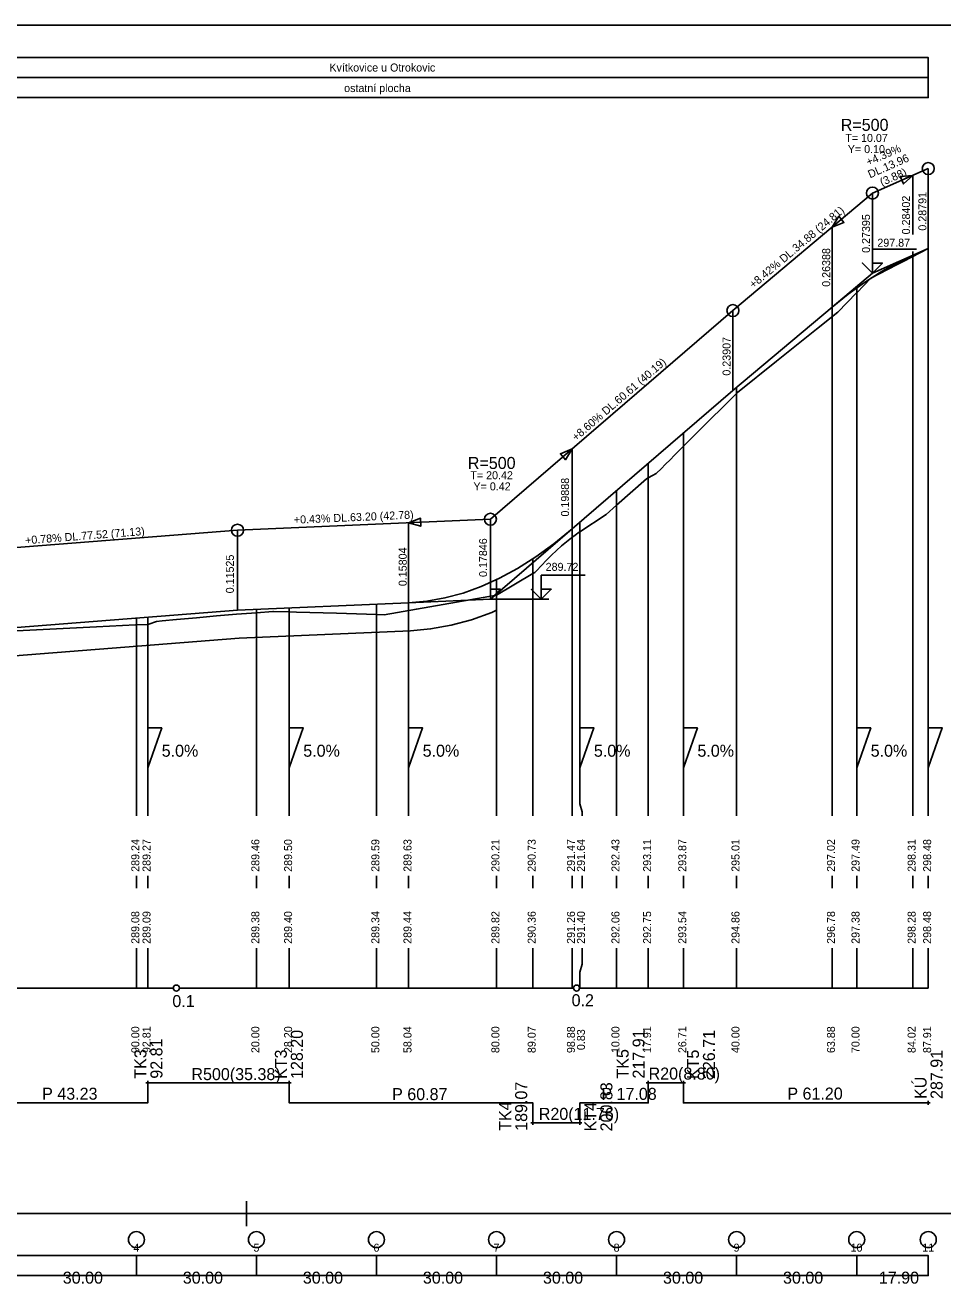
# Model space of a CAD drawing. Extents: x -261.5 to -198.5, y 150.1 to 181.6.
# Drawn here: x -246.01 to -223.08, y 150.11 to 181.57 of the extents above; entities that cross this region are included whole.
import ezdxf

# ---------------------------------------------------------------- set-up
doc = ezdxf.new("R2010")
doc.units = 0
for name, color, linetype in [('_drenaz', 7, 'Continuous'), ('KOTA', 7, 'Continuous'), ('NOVY_STAV', 7, 'Continuous'), ('NS_OBLOUK', 7, 'Continuous'), ('REZY_PO', 7, 'Continuous'), ('SESTAVY_REZU_PO', 7, 'Continuous'), ('SKLONOVE_POMERY', 7, 'Continuous'), ('SMEROVE_POMERY', 7, 'Continuous'), ('SMEROVE_POMERY_KOD', 7, 'Continuous'), ('SVK_STAT', 7, 'Continuous'), ('TABULKY', 7, 'Continuous'), ('u_pricne_rezy', 7, 'Continuous'), ('x_formát_rám', 7, 'Continuous')]:
    doc.layers.add(name, color=color, linetype=linetype)

msp = doc.modelspace()

# ---------------------------------------------------------------- linework, layer by layer
at = {"layer": '_drenaz'}
msp.add_lwpolyline([(-251.082, 165.262), (-249.001, 165.558), (-248.689, 165.6), (-248.381, 165.636), (-248.072, 165.668), (-247.761, 165.694), (-240.663, 166.249), (-236.381, 166.435), (-235.88, 166.48), (-235.366, 166.572), (-234.855, 166.71), (-234.348, 166.893), (-234.231, 166.946)], dxfattribs=at)
at = {"layer": 'KOTA'}
msp.add_line((-234.385, 167.222), (-232.92, 167.222), dxfattribs=at)
for points in [[(-224.836, 175.375), (-225.086, 175.625), (-224.836, 175.375), (-224.836, 175.975), (-223.736, 175.975)], [(-224.836, 175.625), (-224.836, 175.375), (-224.586, 175.625), (-224.836, 175.625)], [(-224.836, 175.375), (-224.586, 175.625), (-224.836, 175.625)], [(-224.836, 175.375), (-224.836, 175.375)], [(-233.112, 167.222), (-233.362, 167.472), (-233.112, 167.222), (-233.112, 167.822), (-232.012, 167.822)], [(-234.385, 167.222), (-234.135, 167.472), (-234.385, 167.472)], [(-233.112, 167.472), (-233.112, 167.222), (-232.862, 167.472), (-233.112, 167.472)], [(-234.385, 167.222), (-234.385, 167.222)]]:
    msp.add_lwpolyline(points, dxfattribs=at)
at = {"layer": 'NOVY_STAV'}
for points in [[(-224.836, 177.375), (-223.44, 177.988)], [(-223.44, 175.988), (-223.44, 177.988)], [(-228.324, 174.437), (-224.836, 177.375)], [(-224.836, 175.375), (-224.836, 177.375)], [(-247.818, 166.392), (-240.705, 166.948), (-236.427, 167.134), (-235.973, 167.174), (-235.519, 167.256), (-235.065, 167.378), (-234.612, 167.542), (-234.158, 167.747), (-233.704, 167.993), (-233.25, 168.281), (-232.796, 168.609), (-232.343, 168.979), (-228.324, 172.437), (-225.843, 174.526), (-225.44, 174.849), (-225.037, 175.14), (-224.634, 175.398), (-224.231, 175.624), (-223.828, 175.817), (-223.44, 175.988)], [(-225.843, 174.526), (-224.836, 175.375), (-223.44, 175.988)], [(-234.385, 169.222), (-228.324, 174.437)], [(-228.324, 172.437), (-228.324, 174.437)], [(-248.457, 168.342), (-240.705, 168.948)], [(-240.705, 168.948), (-234.385, 169.222)], [(-240.705, 166.948), (-240.705, 168.948)], [(-236.427, 167.134), (-234.385, 167.222), (-232.343, 168.979), (-232.343, 168.979)], [(-234.385, 167.222), (-234.385, 169.222)]]:
    msp.add_lwpolyline(points, dxfattribs=at)
for centre in [(-223.44, 177.988), (-224.836, 177.375), (-228.324, 174.437), (-234.385, 169.222), (-240.705, 168.948)]:
    msp.add_circle(centre, 0.15, dxfattribs=at)
at = {"layer": 'NS_OBLOUK'}
for points in [[(-224.063, 177.605), (-223.828, 177.817), (-224.143, 177.788), (-224.063, 177.605)], [(-223.828, 176.336), (-223.828, 177.817)], [(-225.843, 176.526), (-225.549, 176.643), (-225.678, 176.796), (-225.843, 176.526)], [(-225.843, 174.526), (-225.843, 176.526)], [(-223.828, 175.817), (-223.828, 175.914)], [(-232.505, 170.708), (-232.343, 170.979), (-232.635, 170.859), (-232.505, 170.708)], [(-232.343, 168.979), (-232.343, 170.979)], [(-236.427, 169.134), (-236.123, 169.047), (-236.131, 169.247), (-236.427, 169.134)], [(-236.427, 167.134), (-236.427, 169.134)]]:
    msp.add_lwpolyline(points, dxfattribs=at)
for points in [[(-223.828, 177.817), (-224.143, 177.788), (-224.063, 177.605)], [(-225.843, 176.526), (-225.678, 176.796), (-225.549, 176.643)], [(-232.343, 170.979), (-232.635, 170.859), (-232.505, 170.708)], [(-236.427, 169.134), (-236.131, 169.247), (-236.123, 169.047)]]:
    msp.add_lwpolyline(points, close=True, dxfattribs=at)
at = {"layer": 'REZY_PO'}
msp.add_lwpolyline([(-246.231, 166.433), (-245.231, 166.485), (-244.231, 166.536), (-243.251, 166.586), (-243.231, 166.587), (-243.231, 166.587), (-242.949, 166.595), (-242.921, 166.596), (-242.733, 166.666), (-242.59, 166.68), (-242.231, 166.715), (-241.731, 166.761), (-241.231, 166.805), (-240.731, 166.847), (-240.231, 166.887), (-240.231, 166.887), (-240.231, 166.887), (-239.821, 166.918), (-239.806, 166.919), (-239.411, 166.907), (-239.231, 166.902), (-238.231, 166.871), (-237.231, 166.841), (-237.231, 166.841), (-237.039, 166.835), (-236.231, 166.976), (-235.231, 167.15), (-234.232, 167.324), (-234.231, 167.325), (-234.231, 167.325), (-233.323, 167.865), (-233.277, 167.893), (-233.259, 167.904), (-233.231, 167.936), (-233.106, 168.07), (-232.981, 168.199), (-232.856, 168.323), (-232.731, 168.442), (-232.606, 168.554), (-232.481, 168.66), (-232.356, 168.759), (-232.231, 168.85), (-232.189, 168.879), (-232.147, 168.907), (-231.492, 169.34), (-231.231, 169.571), (-231.23, 169.571), (-230.48, 170.233), (-230.439, 170.256), (-230.439, 170.256), (-230.439, 170.256), (-230.335, 170.314), (-230.241, 170.365), (-230.231, 170.375), (-230.119, 170.486), (-230.007, 170.598), (-229.895, 170.71), (-229.783, 170.823), (-229.672, 170.935), (-229.56, 171.047), (-229.56, 171.047), (-229.56, 171.047), (-229.231, 171.374), (-228.231, 172.369), (-228.23, 172.369), (-228.209, 172.391), (-227.231, 173.172), (-226.231, 173.972), (-225.697, 174.398), (-225.231, 174.881), (-225.23, 174.882), (-224.878, 175.246), (-224.231, 175.581), (-224.065, 175.666), (-223.44, 175.988)], dxfattribs=at)
at = {"layer": 'SESTAVY_REZU_PO'}
for points in [[(-255.634, 157.506), (-242.306, 157.506)], [(-242.156, 157.506), (-232.306, 157.506)], [(-232.156, 157.506), (-223.44, 157.506)]]:
    msp.add_lwpolyline(points, dxfattribs=at)
for centre in [(-242.231, 157.506), (-232.231, 157.506)]:
    msp.add_circle(centre, 0.075, dxfattribs=at)
at = {"layer": 'SMEROVE_POMERY'}
for points in [[(-242.949, 164.006), (-242.949, 163.006), (-242.949, 163.006), (-242.774, 163.506), (-242.599, 164.006), (-242.949, 164.006)], [(-239.411, 164.006), (-239.411, 163.006), (-239.411, 163.006), (-239.236, 163.506), (-239.061, 164.006), (-239.411, 164.006)], [(-236.427, 164.006), (-236.427, 163.006), (-236.427, 163.006), (-236.252, 163.506), (-236.077, 164.006), (-236.427, 164.006)], [(-232.147, 164.006), (-232.147, 163.006), (-232.147, 163.006), (-231.972, 163.506), (-231.797, 164.006), (-232.147, 164.006)], [(-229.56, 164.006), (-229.56, 163.006), (-229.56, 163.006), (-229.385, 163.506), (-229.21, 164.006), (-229.56, 164.006)], [(-225.23, 164.006), (-225.23, 163.006), (-225.23, 163.006), (-225.055, 163.506), (-224.88, 164.006), (-225.23, 164.006)], [(-223.44, 164.006), (-223.44, 163.006), (-223.44, 163.006), (-223.265, 163.506), (-223.09, 164.006), (-223.44, 164.006)], [(-252.231, 154.633), (-251.699, 154.633), (-251.699, 154.133), (-250.467, 154.133), (-250.467, 154.633), (-249.199, 154.633), (-249.199, 154.133), (-247.272, 154.133), (-247.272, 154.633), (-242.949, 154.633), (-242.949, 155.133), (-239.411, 155.133), (-239.411, 154.633), (-233.323, 154.633), (-233.323, 154.133), (-232.147, 154.133), (-232.147, 154.633), (-230.439, 154.633), (-230.439, 155.133), (-229.56, 155.133), (-229.56, 154.633), (-223.44, 154.633)]]:
    msp.add_lwpolyline(points, dxfattribs=at)
at = {"layer": 'SMEROVE_POMERY_KOD'}
for points in [[(-242.999, 155.133), (-242.899, 155.133)], [(-242.949, 155.083), (-242.949, 155.183)], [(-239.461, 155.133), (-239.361, 155.133)], [(-239.411, 155.083), (-239.411, 155.183)], [(-230.489, 155.133), (-230.389, 155.133)], [(-230.439, 155.083), (-230.439, 155.183)], [(-229.61, 155.133), (-229.51, 155.133)], [(-229.56, 155.083), (-229.56, 155.183)], [(-223.49, 154.633), (-223.39, 154.633)], [(-223.44, 154.583), (-223.44, 154.683)], [(-233.323, 154.083), (-233.323, 154.183)], [(-232.147, 154.083), (-232.147, 154.183)], [(-233.373, 154.133), (-233.273, 154.133)], [(-232.197, 154.133), (-232.097, 154.133)]]:
    msp.add_lwpolyline(points, dxfattribs=at)
at = {"layer": 'SVK_STAT'}
for points in [[(-223.44, 161.806), (-223.44, 175.988)], [(-223.828, 161.806), (-223.828, 175.817)], [(-225.23, 161.806), (-225.23, 175)], [(-225.843, 161.806), (-225.843, 174.526)], [(-228.23, 161.806), (-228.23, 172.515)], [(-229.56, 161.806), (-229.56, 171.373)], [(-230.439, 161.806), (-230.439, 170.616)], [(-231.23, 161.806), (-231.23, 169.936)], [(-232.343, 161.806), (-232.343, 168.979)], [(-232.093, 161.806), (-232.093, 161.906), (-232.147, 162.106), (-232.147, 169.147)], [(-233.323, 161.806), (-233.323, 168.234)], [(-234.231, 161.806), (-234.231, 167.714)], [(-237.231, 161.806), (-237.231, 167.099)], [(-236.427, 161.806), (-236.427, 167.134)], [(-243.231, 161.806), (-243.231, 166.751)], [(-242.949, 161.806), (-242.949, 166.773)], [(-240.231, 161.806), (-240.231, 166.969)], [(-239.411, 161.806), (-239.411, 167.004)], [(-243.231, 160.006), (-243.231, 160.306)], [(-242.949, 160.006), (-242.949, 160.306)], [(-240.231, 160.006), (-240.231, 160.306)], [(-239.411, 160.006), (-239.411, 160.306)], [(-237.231, 160.006), (-237.231, 160.306)], [(-236.427, 160.006), (-236.427, 160.306)], [(-234.231, 160.006), (-234.231, 160.306)], [(-233.323, 160.006), (-233.323, 160.306)], [(-232.343, 160.006), (-232.343, 160.306)], [(-232.093, 160.006), (-232.093, 160.306)], [(-231.23, 160.006), (-231.23, 160.306)], [(-230.439, 160.006), (-230.439, 160.306)], [(-229.56, 160.006), (-229.56, 160.306)], [(-228.23, 160.006), (-228.23, 160.306)], [(-225.843, 160.006), (-225.843, 160.306)], [(-225.23, 160.006), (-225.23, 160.306)], [(-223.828, 160.006), (-223.828, 160.306)], [(-223.44, 160.006), (-223.44, 160.306)], [(-243.231, 157.506), (-243.231, 158.506)], [(-242.949, 157.506), (-242.949, 158.506)], [(-240.231, 157.506), (-240.231, 158.506)], [(-239.411, 157.506), (-239.411, 158.506)], [(-237.231, 157.506), (-237.231, 158.506)], [(-236.427, 157.506), (-236.427, 158.506)], [(-234.231, 157.506), (-234.231, 158.506)], [(-233.323, 157.506), (-233.323, 158.506)], [(-232.343, 157.506), (-232.343, 158.506)], [(-232.147, 157.506), (-232.147, 157.906), (-232.093, 158.106), (-232.093, 158.506)], [(-231.23, 157.506), (-231.23, 158.506)], [(-230.439, 157.506), (-230.439, 158.506)], [(-229.56, 157.506), (-229.56, 158.506)], [(-228.23, 157.506), (-228.23, 158.506)], [(-225.843, 157.506), (-225.843, 158.506)], [(-225.23, 157.506), (-225.23, 158.506)], [(-223.828, 157.506), (-223.828, 158.506)], [(-223.44, 157.506), (-223.44, 158.506)]]:
    msp.add_lwpolyline(points, dxfattribs=at)
at = {"layer": 'TABULKY'}
for points in [[(-252.231, 179.76), (-223.44, 179.76), (-223.44, 180.76), (-252.231, 180.76), (-252.231, 179.76)], [(-252.231, 180.26), (-223.44, 180.26)]]:
    msp.add_lwpolyline(points, dxfattribs=at)
at = {"layer": 'u_pricne_rezy'}
for points in [[(-252.231, 150.317), (-223.44, 150.317), (-223.44, 150.817), (-252.231, 150.817), (-252.231, 150.317)], [(-243.231, 150.317), (-243.231, 150.817)], [(-240.231, 150.317), (-240.231, 150.817)], [(-237.231, 150.317), (-237.231, 150.817)], [(-234.231, 150.317), (-234.231, 150.817)], [(-231.23, 150.317), (-231.23, 150.817)], [(-228.23, 150.317), (-228.23, 150.817)], [(-225.23, 150.317), (-225.23, 150.817)]]:
    msp.add_lwpolyline(points, dxfattribs=at)
for centre in [(-243.231, 151.217), (-240.231, 151.217), (-237.231, 151.217), (-234.231, 151.217), (-231.23, 151.217), (-228.23, 151.217), (-225.23, 151.217), (-223.44, 151.217)]:
    msp.add_circle(centre, 0.2, dxfattribs=at)
at = {"layer": 'x_formát_rám'}
msp.add_line((-240.476, 152.183), (-240.476, 151.558), dxfattribs=at)
msp.add_lwpolyline([(-261.476, 151.871), (-198.476, 151.871), (-198.476, 181.571), (-261.476, 181.571)], close=True, dxfattribs=at)

# ---------------------------------------------------------------- texts
at = {"layer": 'KOTA'}
for s, p in [('297.87', (-224.713, 176.034)), ('289.72', (-233.003, 167.933))]:
    msp.add_text(s, height=0.2, dxfattribs=at).set_placement(p)
at = {"layer": 'NOVY_STAV'}
for s, rotation, p in [('+4.39%', 23.7149, (-224.938, 178.05)), ('DL.13.96', 23.7149, (-224.896, 177.741)), ('(3.88)', 23.7149, (-224.597, 177.544)), (' 0.28791', 90, (-223.488, 176.361)), ('+8.42% DL.34.88 (24.81)', 40.1057, (-227.81, 174.982)), (' 0.27395', 90, (-224.897, 175.805)), (' 0.23907', 90, (-228.382, 172.737)), ('+8.60% DL.60.61 (40.19)', 40.7045, (-232.243, 171.166)), ('+0.43% DL.63.20 (42.78)', 2.4868, (-239.292, 169.109)), ('+0.78% DL.77.52 (71.13)', 4.4694, (-246.005, 168.595)), (' 0.17846', 90, (-234.468, 167.705)), (' 0.11525', 90, (-240.795, 167.297))]:
    msp.add_text(s, height=0.2, rotation=rotation, dxfattribs=at).set_placement(p)
at = {"layer": 'NS_OBLOUK'}
for s, height, p in [('R=500', 0.3, (-225.628, 178.93)), ('T= 10.07', 0.2, (-225.515, 178.653)), ('Y= 0.10', 0.2, (-225.452, 178.374)), ('R=500', 0.3, (-234.948, 170.479)), ('T= 20.42', 0.2, (-234.885, 170.222)), ('Y= 0.42', 0.2, (-234.807, 169.944))]:
    msp.add_text(s, height=height, dxfattribs=at).set_placement(p)
for s, p in [(' 0.28402', (-223.897, 176.268)), (' 0.26388', (-225.892, 174.958)), (' 0.19888', (-232.419, 169.216)), (' 0.15804', (-236.476, 167.476))]:
    msp.add_text(s, height=0.2, rotation=90, dxfattribs=at).set_placement(p)
at = {"layer": 'SESTAVY_REZU_PO'}
for s, p in [('0.1', (-242.333, 157.03)), ('0.2', (-232.354, 157.051))]:
    msp.add_text(s, height=0.3, dxfattribs=at).set_placement(p)
at = {"layer": 'SKLONOVE_POMERY'}
for p in [(-242.599, 163.287), (-239.061, 163.287), (-236.077, 163.287), (-231.797, 163.287), (-229.21, 163.287), (-224.88, 163.287)]:
    msp.add_text('5.0%', height=0.3, dxfattribs=at).set_placement(p)
at = {"layer": 'SMEROVE_POMERY'}
for s, p in [('R500(35.38)', (-241.856, 155.204)), ('R20(8.80)', (-230.43, 155.218)), ('P 43.23', (-245.587, 154.715)), ('P 60.87', (-236.84, 154.704)), ('P 17.08', (-231.611, 154.711)), ('P 61.20', (-226.962, 154.718)), ('R20(11.76)', (-233.174, 154.211))]:
    msp.add_text(s, height=0.3, dxfattribs=at).set_placement(p)
at = {"layer": 'SMEROVE_POMERY_KOD'}
for s, p in [('128.20', (-239.071, 155.233)), ('217.91', (-230.529, 155.244)), ('226.71', (-228.772, 155.23)), ('92.81', (-242.581, 155.24)), ('TK3', (-242.981, 155.24)), ('KT3', (-239.471, 155.233)), ('TK5', (-230.929, 155.244)), ('KT5', (-229.172, 155.23)), ('287.91', (-223.084, 154.733)), ('189.07', (-233.465, 153.937)), ('200.83', (-231.335, 153.923)), ('KÚ', (-223.484, 154.733)), ('TK4', (-233.865, 153.937)), ('KT4', (-231.735, 153.923))]:
    msp.add_text(s, height=0.3, rotation=90, dxfattribs=at).set_placement(p)
at = {"layer": 'SVK_STAT'}
for s, p in [(' 289.24', (-243.159, 160.336)), (' 289.27', (-242.878, 160.336)), (' 289.46', (-240.159, 160.336)), (' 289.50', (-239.34, 160.336)), (' 289.59', (-237.159, 160.336)), (' 289.63', (-236.356, 160.336)), (' 290.21', (-234.159, 160.336)), (' 290.73', (-233.252, 160.336)), (' 291.47', (-232.271, 160.336)), (' 291.64', (-232.021, 160.336)), (' 292.43', (-231.159, 160.336)), (' 293.11', (-230.368, 160.336)), (' 293.87', (-229.489, 160.336)), (' 295.01', (-228.159, 160.336)), (' 297.02', (-225.772, 160.336)), (' 297.49', (-225.159, 160.336)), (' 298.31', (-223.757, 160.336)), (' 298.48', (-223.369, 160.336)), (' 289.08', (-243.159, 158.536)), (' 289.09', (-242.878, 158.536)), (' 289.38', (-240.159, 158.536)), (' 289.40', (-239.34, 158.536)), (' 289.34', (-237.159, 158.536)), (' 289.44', (-236.356, 158.536)), (' 289.82', (-234.159, 158.536)), (' 290.36', (-233.252, 158.536)), (' 291.26', (-232.271, 158.536)), (' 291.40', (-232.021, 158.536)), (' 292.06', (-231.159, 158.536)), (' 292.75', (-230.368, 158.536)), (' 293.54', (-229.489, 158.536)), (' 294.86', (-228.159, 158.536)), (' 296.78', (-225.772, 158.536)), (' 297.38', (-225.159, 158.536)), (' 298.28', (-223.757, 158.536)), (' 298.48', (-223.369, 158.536)), (' 90.00', (-243.159, 155.806)), (' 92.81', (-242.878, 155.806)), (' 20.00', (-240.159, 155.806)), (' 28.20', (-239.34, 155.806)), (' 50.00', (-237.159, 155.806)), (' 58.04', (-236.356, 155.806)), (' 80.00', (-234.159, 155.806)), (' 89.07', (-233.252, 155.806)), (' 98.88', (-232.271, 155.806)), ('  0.83', (-232.021, 155.806)), (' 10.00', (-231.159, 155.806)), (' 17.91', (-230.368, 155.806)), (' 26.71', (-229.489, 155.806)), (' 40.00', (-228.159, 155.806)), (' 63.88', (-225.772, 155.806)), (' 70.00', (-225.159, 155.806)), (' 84.02', (-223.757, 155.806)), (' 87.91', (-223.369, 155.806))]:
    msp.add_text(s, height=0.2, rotation=90, dxfattribs=at).set_placement(p)
at = {"layer": 'TABULKY'}
for s, p in [('Kvítkovice u Otrokovic', (-238.408, 180.412)), ('ostatní plocha', (-238.04, 179.899))]:
    msp.add_text(s, height=0.2, dxfattribs=at).set_placement(p)
at = {"layer": 'u_pricne_rezy'}
for s, height, p in [('4', 0.2, (-243.306, 150.917)), ('5', 0.2, (-240.306, 150.917)), ('6', 0.2, (-237.306, 150.917)), ('7', 0.2, (-234.306, 150.917)), ('8', 0.2, (-231.305, 150.917)), ('9', 0.2, (-228.306, 150.917)), ('10', 0.2, (-225.381, 150.917)), ('11', 0.2, (-223.591, 150.917)), ('30.00', 0.3, (-245.071, 150.117)), ('30.00', 0.3, (-242.071, 150.117)), ('30.00', 0.3, (-239.071, 150.117)), ('30.00', 0.3, (-236.071, 150.117)), ('30.00', 0.3, (-233.07, 150.117)), ('30.00', 0.3, (-230.07, 150.117)), ('30.00', 0.3, (-227.07, 150.117)), ('17.90', 0.3, (-224.675, 150.117))]:
    msp.add_text(s, height=height, dxfattribs=at).set_placement(p)

doc.saveas('drawing.dxf')
